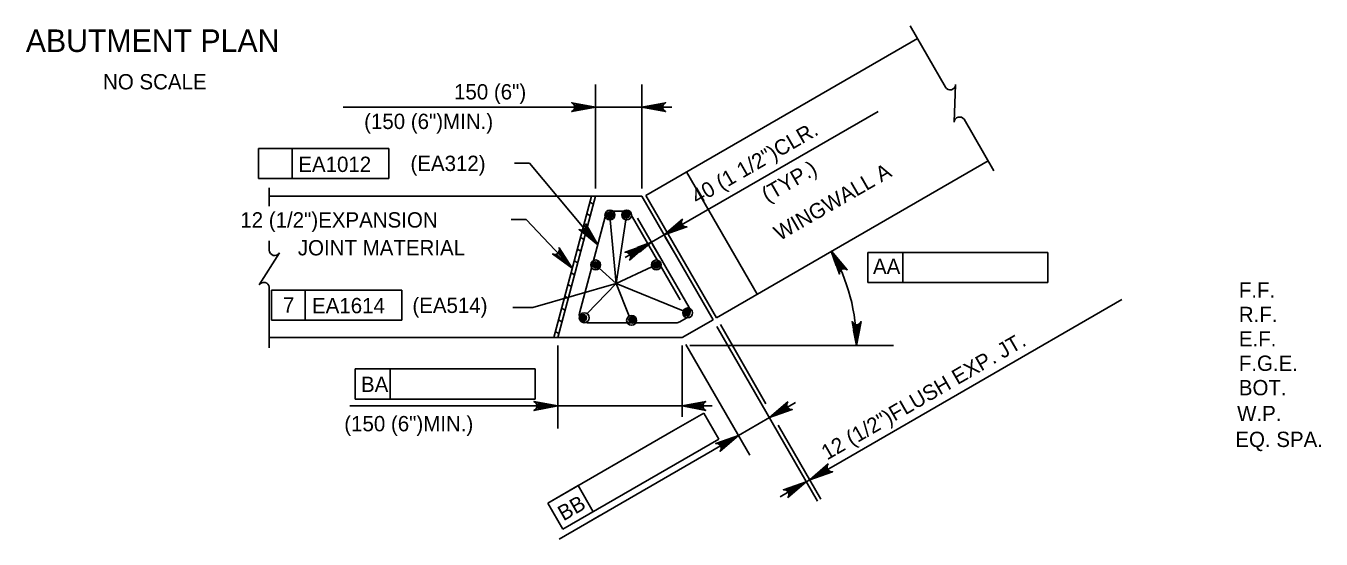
# Model space of a CAD drawing. Extents: x 634540 to 640306, y 296059 to 300275.
# Drawn here: x 638692.5 to 638946.3, y 296927.2 to 297027.7 of the extents above; entities that cross this region are included whole.
import ezdxf

# ---------------------------------------------------------------- set-up
doc = ezdxf.new("R2010")
doc.units = 0
for name, color, linetype in [('10', 7, 'Continuous'), ('3', 7, 'Continuous'), ('4', 7, 'Continuous'), ('5', 7, 'Continuous')]:
    doc.layers.add(name, color=color, linetype=linetype)

msp = doc.modelspace()

# ---------------------------------------------------------------- linework, layer by layer
at = {"layer": '10'}
for p, q in [((638813.96, 296994.52), (638867.19, 297025.26)), ((638827.81, 296970.55), (638881.03, 297001.28)), ((638821.95, 296999.14), (638835.8, 296975.16)), ((638740.18, 296994.34), (638813.18, 296994.34)), ((638803.32, 296994.34), (638795.91, 296966.65)), ((638804.12, 296994.34), (638796.7, 296966.65)), ((638803.02, 296993.21), (638803.71, 296992.81)), ((638813.18, 296994.34), (638827.14, 296970.16)), ((638813.96, 296994.52), (638827.81, 296970.55)), ((638802.4, 296990.91), (638803.1, 296990.51)), ((638801.79, 296988.6), (638802.48, 296988.2)), ((638801.17, 296986.29), (638801.86, 296985.89)), ((638800.55, 296983.98), (638801.24, 296983.59)), ((638799.93, 296981.68), (638800.62, 296981.28)), ((638799.31, 296979.37), (638800.01, 296978.97)), ((638798.7, 296977.06), (638799.39, 296976.66)), ((638798.08, 296974.76), (638798.77, 296974.36)), ((638796.84, 296970.14), (638797.53, 296969.74)), ((638797.46, 296972.45), (638798.15, 296972.05)), ((638821.06, 296966.65), (638827.14, 296970.16)), ((638796.22, 296967.84), (638796.91, 296967.44)), ((638740.18, 296966.65), (638821.06, 296966.65))]:
    msp.add_line(p, q, dxfattribs=at)
at = {"layer": '3'}
for p, q in [((638804.12, 296995.88), (638804.12, 297016.24)), ((638813.18, 296995.88), (638813.18, 297016.24)), ((638804.12, 297011.81), (638754.65, 297011.81)), ((638804.12, 297011.81), (638813.18, 297011.81)), ((638813.18, 297011.81), (638819.09, 297011.81)), ((638822.67, 296989.72), (638859.47, 297010.97)), ((638738.09, 297003.71), (638763.63, 297003.71)), ((638738.09, 296997.8), (638738.09, 297003.71)), ((638744.68, 296997.8), (638744.68, 297003.71)), ((638763.63, 297003.71), (638763.63, 296997.8)), ((638791.17, 297000.85), (638788.22, 297000.85)), ((638804.55, 296984.8), (638791.17, 297000.85)), ((638763.63, 296997.8), (638738.09, 296997.8)), ((638790.51, 296989.78), (638787.56, 296989.78)), ((638799.56, 296980.27), (638790.51, 296989.78)), ((638807.01, 296989.73), (638808.15, 296977.28)), ((638808.15, 296977.28), (638810.06, 296989.73)), ((638817.55, 296986.77), (638822.67, 296989.72)), ((638815.05, 296985.33), (638817.55, 296986.77)), ((638817.79, 296986.35), (638819.77, 296982.93)), ((638814.39, 296984.94), (638809.94, 296982.37)), ((638815.3, 296984.91), (638817.27, 296981.49)), ((638857.47, 296977.43), (638857.47, 296983.33)), ((638885.92, 296983.33), (638857.47, 296983.33)), ((638864.31, 296983.33), (638857.47, 296983.33)), ((638864.31, 296977.43), (638864.31, 296983.33)), ((638892.77, 296983.33), (638885.92, 296983.33)), ((638892.77, 296977.43), (638892.77, 296983.33)), ((638808.15, 296977.28), (638815.14, 296980.49)), ((638804.85, 296980.25), (638808.15, 296977.28)), ((638740.61, 296975.98), (638766.15, 296975.98)), ((638740.61, 296970.07), (638740.61, 296975.98)), ((638747.2, 296970.07), (638747.2, 296975.98)), ((638766.15, 296975.98), (638766.15, 296970.07)), ((638808.15, 296977.28), (638791.82, 296972.53)), ((638802.44, 296971.33), (638808.15, 296977.28)), ((638810.7, 296970.85), (638808.15, 296977.28)), ((638808.15, 296977.28), (638821.26, 296971.87)), ((638857.47, 296977.43), (638892.77, 296977.43)), ((638851.19, 296941.75), (638907.27, 296974.13)), ((638791.82, 296972.53), (638787.88, 296972.53)), ((638766.15, 296970.07), (638740.61, 296970.07)), ((638827.91, 296968.83), (638847.62, 296934.58)), ((638828.57, 296969.22), (638837.51, 296953.7)), ((638796.7, 296965.12), (638796.7, 296948.83)), ((638821.06, 296965.12), (638821.06, 296951.13)), ((638821.83, 296965.32), (638834.35, 296943.64)), ((638822.6, 296965.12), (638862.5, 296965.12)), ((638757, 296960.5), (638757, 296954.59)), ((638785.45, 296960.5), (638757, 296960.5)), ((638757, 296954.59), (638757, 296960.5)), ((638763.84, 296960.5), (638757, 296960.5)), ((638763.84, 296954.59), (638763.84, 296960.5)), ((638792.3, 296960.5), (638785.45, 296960.5)), ((638792.3, 296954.59), (638792.3, 296960.5)), ((638790.8, 296953.26), (638755.94, 296953.26)), ((638757, 296954.59), (638792.3, 296954.59)), ((638765.3, 296953.26), (638762.34, 296953.26)), ((638793.75, 296953.26), (638790.8, 296953.26)), ((638821.06, 296953.26), (638796.7, 296953.26)), ((638824.01, 296953.26), (638826.97, 296953.26)), ((638840.77, 296952.46), (638843.33, 296953.93)), ((638825.34, 296951.87), (638819.41, 296948.44)), ((638828.29, 296946.75), (638825.34, 296951.87)), ((638838.21, 296950.98), (638832.13, 296947.47)), ((638819.41, 296948.44), (638794.77, 296934.22)), ((638839.93, 296949.49), (638848.29, 296934.97)), ((638797.72, 296929.1), (638828.29, 296946.75)), ((638829.58, 296946), (638827.02, 296944.52)), ((638827.02, 296944.52), (638796.96, 296927.17)), ((638848.63, 296940.28), (638851.19, 296941.75)), ((638800.69, 296937.64), (638794.77, 296934.22)), ((638803.65, 296932.53), (638800.69, 296937.64)), ((638845.41, 296938.42), (638846.08, 296938.8)), ((638842.85, 296936.94), (638840.3, 296935.47)), ((638794.77, 296934.22), (638797.72, 296929.1)), ((638797.72, 296929.1), (638794.77, 296934.22)), ((638804.93, 296931.77), (638802.38, 296930.29))]:
    msp.add_line(p, q, dxfattribs=at)
for points in [[(638804.12, 297011.81), (638799.46, 297012.68), (638799.82, 297012.44), (638800.01, 297012.12), (638800.06, 297011.81), (638800.01, 297011.5), (638799.82, 297011.19), (638799.46, 297010.94), (638804.12, 297011.81), (638799.82, 297011.19), (638800.01, 297011.5), (638804.12, 297011.81), (638800.06, 297011.81), (638800.01, 297012.12), (638804.12, 297011.81), (638799.82, 297012.44)], [(638813.18, 297011.81), (638817.84, 297010.94), (638817.48, 297011.19), (638817.3, 297011.5), (638817.24, 297011.81), (638817.3, 297012.12), (638817.48, 297012.44), (638817.84, 297012.68), (638813.18, 297011.81), (638817.48, 297012.44), (638817.3, 297012.12), (638813.18, 297011.81), (638817.24, 297011.81), (638817.3, 297011.5), (638813.18, 297011.81), (638817.48, 297011.19)], [(638804.55, 296984.8), (638802.24, 296988.94), (638802.28, 296988.5), (638802.16, 296988.16), (638801.95, 296987.92), (638801.68, 296987.76), (638801.32, 296987.7), (638800.9, 296987.82), (638804.55, 296984.8), (638801.32, 296987.7), (638801.68, 296987.76), (638804.55, 296984.8), (638801.95, 296987.92), (638802.16, 296988.16), (638804.55, 296984.8), (638802.28, 296988.5)], [(638817.55, 296986.77), (638822.03, 296988.34), (638821.59, 296988.38), (638821.28, 296988.55), (638821.07, 296988.8), (638820.96, 296989.1), (638820.97, 296989.46), (638821.15, 296989.85), (638817.55, 296986.77), (638820.97, 296989.46), (638820.96, 296989.1), (638817.55, 296986.77), (638821.07, 296988.8), (638821.28, 296988.55), (638817.55, 296986.77), (638821.59, 296988.38)], [(638799.56, 296980.27), (638796.98, 296984.25), (638797.05, 296983.82), (638796.95, 296983.47), (638796.76, 296983.21), (638796.49, 296983.03), (638796.14, 296982.95), (638795.71, 296983.04), (638799.56, 296980.27), (638796.14, 296982.95), (638796.49, 296983.03), (638799.56, 296980.27), (638796.76, 296983.21), (638796.95, 296983.47), (638799.56, 296980.27), (638797.05, 296983.82)], [(638814.39, 296984.94), (638809.91, 296983.37), (638810.35, 296983.33), (638810.67, 296983.15), (638810.87, 296982.91), (638810.98, 296982.61), (638810.98, 296982.25), (638810.79, 296981.85), (638814.39, 296984.94), (638810.98, 296982.25), (638810.98, 296982.61), (638814.39, 296984.94), (638810.87, 296982.91), (638810.67, 296983.15), (638814.39, 296984.94), (638810.35, 296983.33)], [(638850.35, 296983.56), (638851.91, 296979.09), (638851.95, 296979.52), (638852.13, 296979.84), (638852.37, 296980.04), (638852.67, 296980.15), (638853.04, 296980.15), (638853.43, 296979.96), (638850.35, 296983.56), (638853.04, 296980.15), (638852.67, 296980.15), (638850.35, 296983.56), (638852.37, 296980.04), (638852.13, 296979.84), (638850.35, 296983.56), (638851.95, 296979.52)], [(638855.27, 296965.12), (638856.15, 296969.78), (638855.9, 296969.42), (638855.59, 296969.23), (638855.27, 296969.18), (638854.96, 296969.23), (638854.65, 296969.42), (638854.4, 296969.78), (638855.27, 296965.12), (638854.65, 296969.42), (638854.96, 296969.23), (638855.27, 296965.12), (638855.27, 296969.18), (638855.59, 296969.23), (638855.27, 296965.12), (638855.9, 296969.42)], [(638796.7, 296953.26), (638792.04, 296954.13), (638792.4, 296953.88), (638792.59, 296953.57), (638792.64, 296953.26), (638792.59, 296952.94), (638792.4, 296952.63), (638792.04, 296952.38), (638796.7, 296953.26), (638792.4, 296952.63), (638792.59, 296952.94), (638796.7, 296953.26), (638792.64, 296953.26), (638792.59, 296953.57), (638796.7, 296953.26), (638792.4, 296953.88)], [(638821.06, 296953.26), (638825.72, 296952.38), (638825.36, 296952.63), (638825.18, 296952.94), (638825.12, 296953.26), (638825.18, 296953.57), (638825.36, 296953.88), (638825.72, 296954.13), (638821.06, 296953.26), (638825.36, 296953.88), (638825.18, 296953.57), (638821.06, 296953.26), (638825.12, 296953.26), (638825.18, 296952.94), (638821.06, 296953.26), (638825.36, 296952.63)], [(638838.19, 296950.97), (638842.66, 296952.54), (638842.23, 296952.58), (638841.91, 296952.76), (638841.71, 296953), (638841.6, 296953.3), (638841.6, 296953.66), (638841.79, 296954.06), (638838.19, 296950.97), (638841.6, 296953.66), (638841.6, 296953.3), (638838.19, 296950.97), (638841.71, 296953), (638841.91, 296952.76), (638838.19, 296950.97), (638842.23, 296952.58)], [(638832.13, 296947.47), (638827.66, 296945.9), (638828.1, 296945.87), (638828.41, 296945.69), (638828.62, 296945.44), (638828.72, 296945.14), (638828.72, 296944.78), (638828.53, 296944.39), (638832.13, 296947.47), (638828.72, 296944.78), (638828.72, 296945.14), (638832.13, 296947.47), (638828.62, 296945.44), (638828.41, 296945.69), (638832.13, 296947.47), (638828.1, 296945.87)], [(638846.08, 296938.81), (638850.56, 296940.38), (638850.12, 296940.42), (638849.8, 296940.59), (638849.6, 296940.84), (638849.49, 296941.14), (638849.5, 296941.5), (638849.68, 296941.89), (638846.08, 296938.81), (638849.5, 296941.5), (638849.49, 296941.14), (638846.08, 296938.81), (638849.6, 296940.84), (638849.8, 296940.59), (638846.08, 296938.81), (638850.12, 296940.42)], [(638845.4, 296938.41), (638840.93, 296936.84), (638841.36, 296936.8), (638841.68, 296936.63), (638841.88, 296936.38), (638841.99, 296936.09), (638841.99, 296935.72), (638841.8, 296935.33), (638845.4, 296938.41), (638841.99, 296935.72), (638841.99, 296936.09), (638845.4, 296938.41), (638841.88, 296936.38), (638841.68, 296936.63), (638845.4, 296938.41), (638841.36, 296936.8)]]:
    msp.add_lwpolyline(points, dxfattribs=at)
for points in [[(638801.17, 297012.3), (638801.17, 297011.32), (638804.12, 297011.81)], [(638816.13, 297012.3), (638816.13, 297011.32), (638813.18, 297011.81)], [(638819.86, 296988.67), (638820.35, 296987.82), (638817.55, 296986.77)], [(638803.04, 296987.38), (638802.29, 296986.75), (638804.55, 296984.8)], [(638812.25, 296984.28), (638812.74, 296983.42), (638815.05, 296985.33)], [(638851.25, 296980.78), (638852.13, 296981.24), (638850.31, 296983.62)], [(638797.88, 296982.75), (638797.16, 296982.07), (638799.56, 296980.27)], [(638855.65, 296968.09), (638854.66, 296968.05), (638855.27, 296965.12)], [(638793.75, 296953.75), (638793.75, 296952.77), (638796.7, 296953.26)], [(638824.01, 296953.75), (638824.01, 296952.77), (638821.06, 296953.26)], [(638840.52, 296952.88), (638841.02, 296952.03), (638838.21, 296950.98)], [(638829.33, 296946.42), (638829.82, 296945.57), (638832.13, 296947.47)], [(638848.39, 296940.7), (638848.88, 296939.85), (638846.08, 296938.8)], [(638842.61, 296937.37), (638843.1, 296936.52), (638845.41, 296938.42)]]:
    msp.add_lwpolyline(points, close=True, dxfattribs=at)
for centre in [(638806.93, 296990.68), (638810.21, 296990.68), (638804.14, 296980.9), (638816.01, 296980.9), (638801.9, 296970.54), (638811.17, 296970.02), (638822.15, 296971.5)]:
    msp.add_circle(centre, 0.962, dxfattribs=at)
msp.add_arc((638818.26, 296965.12), 37.01, 0, 29.8962, dxfattribs=at)
at = {"layer": '4'}
for p, q in [((638865.76, 297027.73), (638872.69, 297015.74)), ((638874.68, 297016.27), (638874.4, 297008.85)), ((638876.33, 297009.43), (638882.17, 296999.31)), ((638740.19, 296995.99), (638740.19, 296992.39)), ((638740.19, 296985.61), (638740.19, 296983.8)), ((638742.17, 296983.26), (638738.22, 296976.98)), ((638740.19, 296976.51), (638740.19, 296964.64))]:
    msp.add_line(p, q, dxfattribs=at)
for centre, start, end in [((638873.61, 297016.27), 210, 0), ((638875.46, 297008.81), 35.3286, 177.8672), ((638741.25, 296983.8), 180, 330), ((638739.12, 296976.41), 5.3286, 147.8672)]:
    msp.add_arc(centre, 1.07, start, end, dxfattribs=at)
at = {"layer": '5'}
for p, q in [((638807.51, 296991.45), (638809.74, 296991.45)), ((638811.07, 296990.68), (638820.69, 296974.03)), ((638806.03, 296990.31), (638800.98, 296971.47)), ((638812.32, 296990.06), (638822.43, 296972.55)), ((638820.64, 296969.75), (638821.87, 296970.45)), ((638802.47, 296969.54), (638819.87, 296969.54))]:
    msp.add_line(p, q, dxfattribs=at)
for centre, radius in [((638806.97, 296990.66), 0.625), ((638806.97, 296990.66), 0.469), ((638806.97, 296990.66), 0.313), ((638806.97, 296990.66), 0.156), ((638810.15, 296990.68), 0.625), ((638810.15, 296990.68), 0.469), ((638810.15, 296990.68), 0.313), ((638810.15, 296990.68), 0.156), ((638804.19, 296980.87), 0.625), ((638804.19, 296980.87), 0.469), ((638804.19, 296980.87), 0.313), ((638804.19, 296980.87), 0.156), ((638816.01, 296980.89), 0.625), ((638816.01, 296980.89), 0.469), ((638816.01, 296980.89), 0.313), ((638816.01, 296980.89), 0.156), ((638801.73, 296970.53), 0.625), ((638801.73, 296970.53), 0.469), ((638801.73, 296970.53), 0.313), ((638801.73, 296970.53), 0.156), ((638811.26, 296970.11), 0.625), ((638811.26, 296970.11), 0.469), ((638811.26, 296970.11), 0.313), ((638811.26, 296970.11), 0.156), ((638821.99, 296971.58), 0.625), ((638821.99, 296971.58), 0.469), ((638821.99, 296971.58), 0.313), ((638821.99, 296971.58), 0.156)]:
    msp.add_circle(centre, radius, dxfattribs=at)
for centre, start, end in [((638807.52, 296989.92), 90, 165), ((638809.74, 296989.92), 30, 90), ((638802.47, 296971.08), 165, 270), ((638821.1, 296971.78), 300, 30), ((638819.88, 296971.08), 270, 300)]:
    msp.add_arc(centre, 1.54, start, end, dxfattribs=at)

# ---------------------------------------------------------------- texts
at = {"layer": '3'}
for s, height, p in [('ABUTMENT PLAN', 4.4294, (638692.48, 297022.62)), ('NO SCALE', 3, (638707.61, 297015.29)), ('150 (6")', 3, (638776.39, 297013.32)), ('(150 (6")MIN.)', 3.0001, (638758.77, 297007.53)), ('EA1012', 3, (638745.87, 296999.11)), ('(EA312)', 3, (638767.85, 296999.3)), ('12 (1/2")EXPANSION', 3.0001, (638734.51, 296988.22)), ('JOINT MATERIAL', 3.0001, (638745.78, 296982.76)), ('AA', 3, (638858.48, 296979.11)), ('F.F.', 3, (638930.17, 296974.47)), ('7', 3, (638742.87, 296971.56)), ('EA1614', 3, (638748.56, 296971.43)), ('(EA514)', 3, (638768.23, 296971.48)), ('R.F.', 3, (638930.17, 296969.69)), ('E.F.', 3, (638930.17, 296964.91)), ('F.G.E.', 3, (638930.17, 296960.13)), ('BA', 3, (638758.15, 296956)), ('BOT.', 3, (638930.17, 296955.35)), ('W.P.', 3, (638929.83, 296950.28)), ('(150 (6")MIN.)', 3.0001, (638754.88, 296948.29)), ('EQ. SPA.', 3, (638929.49, 296945.21))]:
    msp.add_text(s, height=height, dxfattribs=at).set_placement(p)
for s, height, rotation, p in [(' 40 (1 1/2")CLR.', 3.0001, 30.0018, (638823.05, 296992.12)), ('(TYP.)', 3, 30.0018, (638837.78, 296993.09)), ('WINGWALL A', 3, 30, (638840.19, 296985.55)), ('12 (1/2")FLUSH EXP. JT.', 3.0001, 30.0031, (638849.48, 296942.56)), ('BB', 3, 30, (638797.83, 296930.63))]:
    msp.add_text(s, height=height, rotation=rotation, dxfattribs=at).set_placement(p)

doc.saveas('drawing.dxf')
